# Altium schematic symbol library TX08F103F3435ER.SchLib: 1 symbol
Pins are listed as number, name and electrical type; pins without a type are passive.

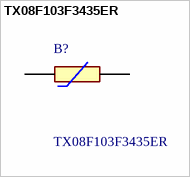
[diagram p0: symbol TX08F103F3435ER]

## TX08F103F3435ER
designator B?
NTC Thermistors THERMISTOR 0805 10K/3435; Manufacturer_Name: Ohmite; Geometry.Height: 0.65mm
footprint THRMC2012X65N
pins: 1, 2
